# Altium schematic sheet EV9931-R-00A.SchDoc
size A3
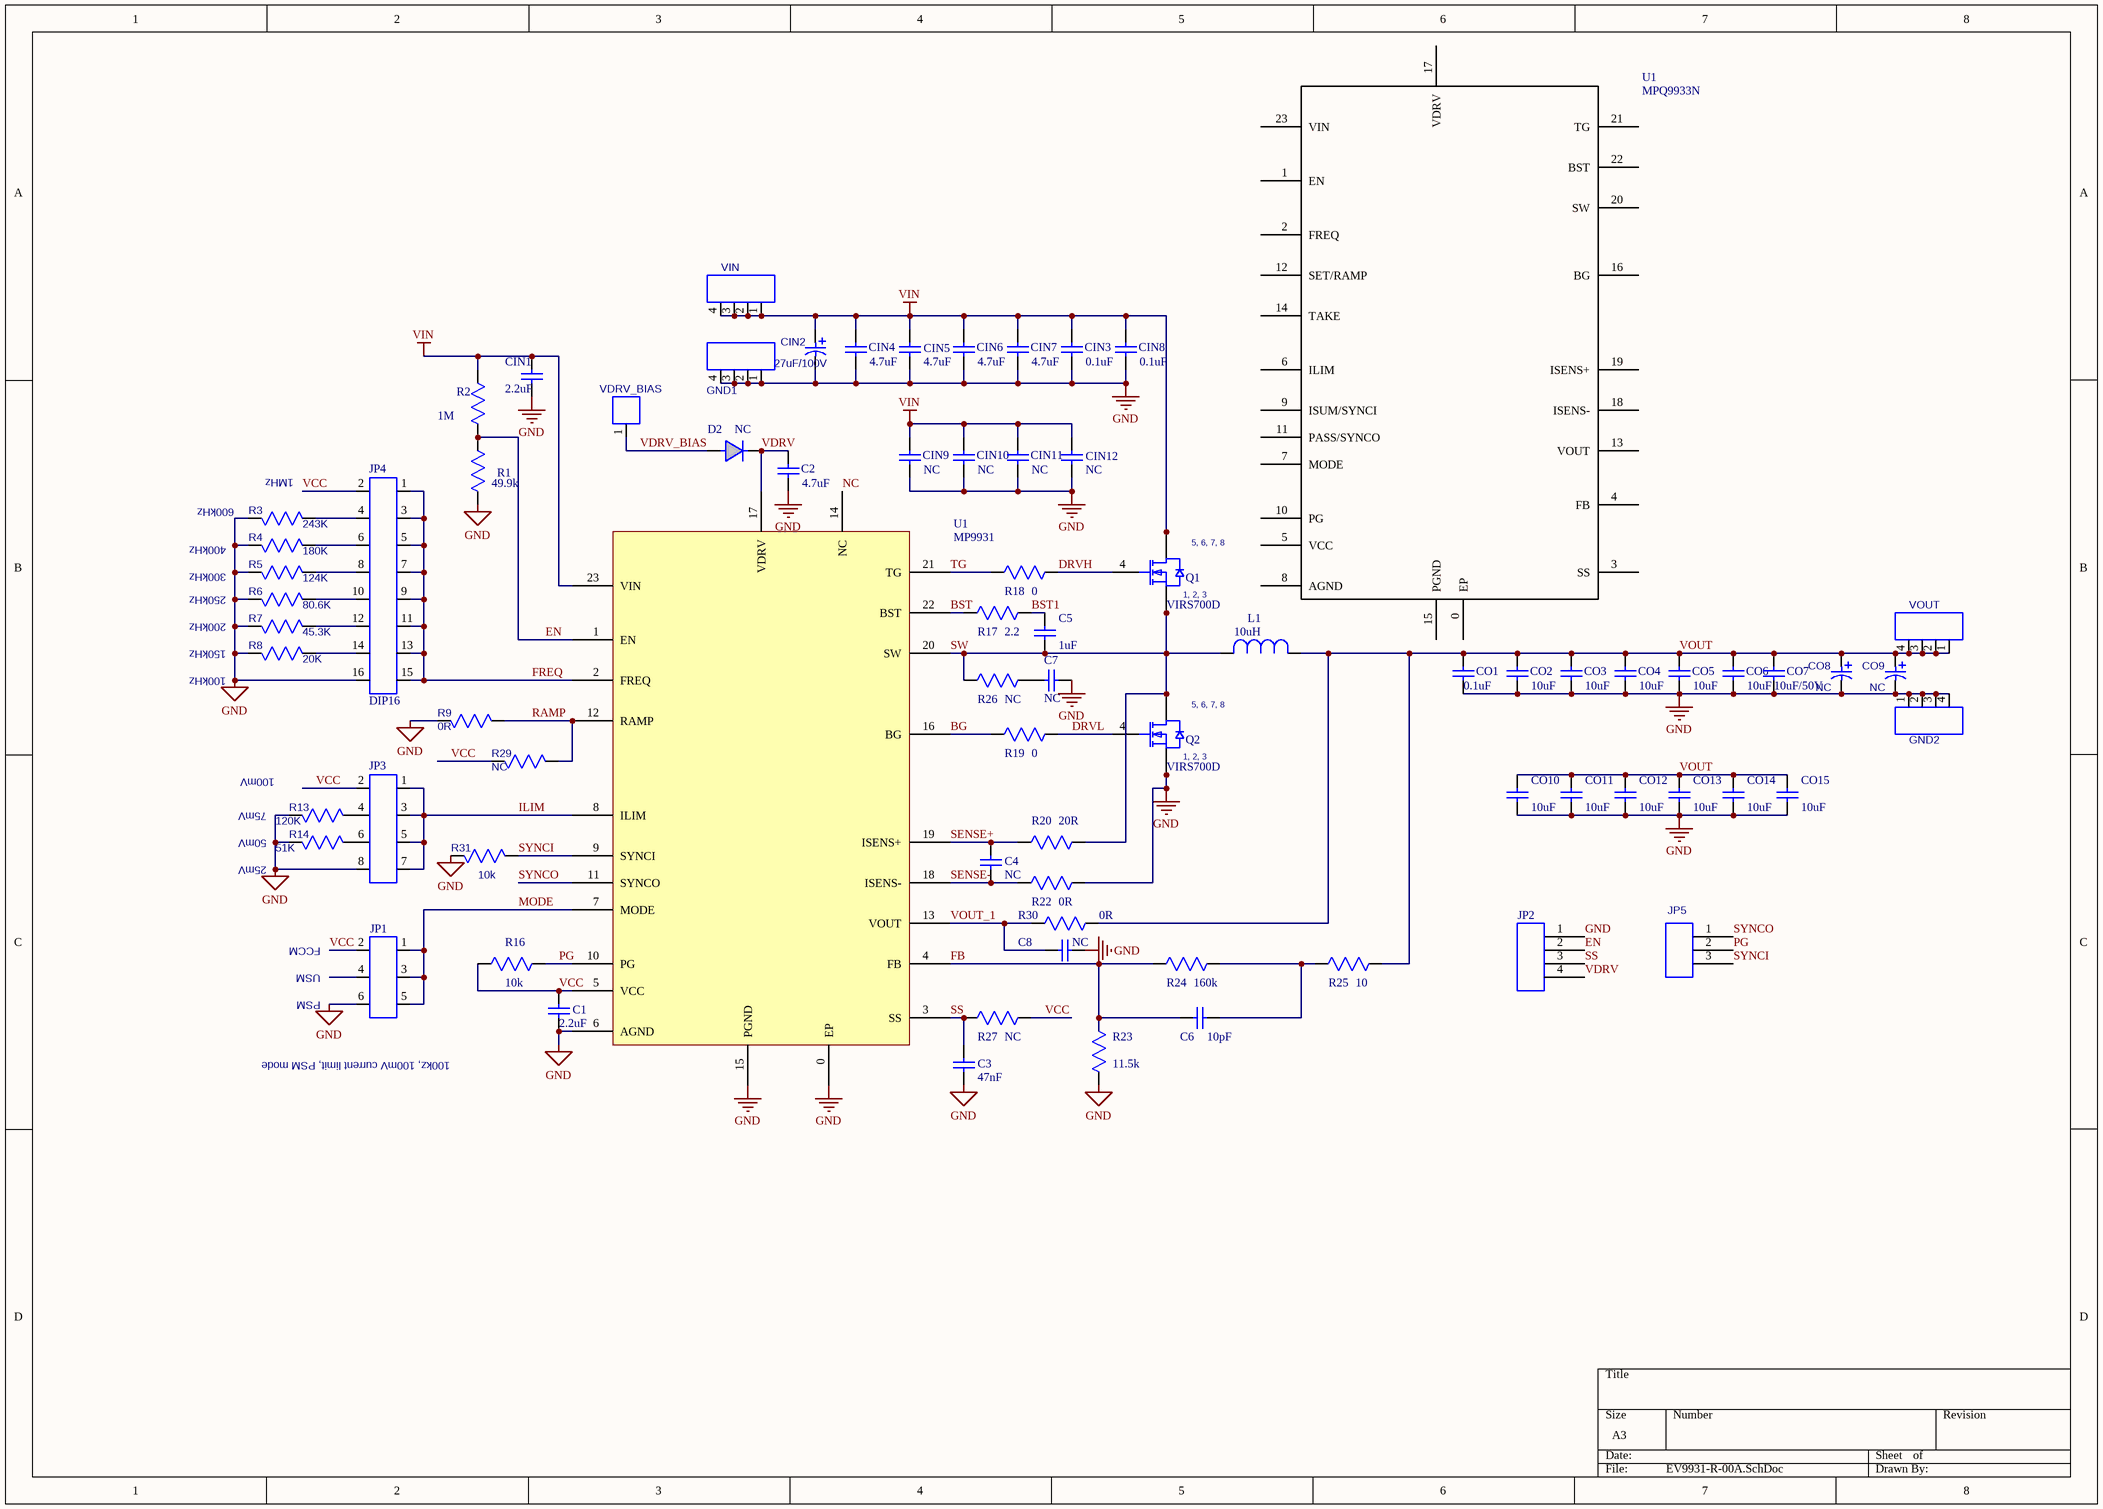
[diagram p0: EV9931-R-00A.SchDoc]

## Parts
(Parts that share a designator on the sheet are numbered #1, #2 ... from top to bottom, then left to right.)
C1  value 2.2uF  [CAP/0603]  (hidden comment: 0603)
C2  value 4.7uF  [CAP/0603]  (hidden comment: 0603)
C3  value 47nF  [CAP/0603]  (hidden comment: 0402)
C4  value NC  [CAP/0603]  (hidden comment: 0402)
C5  value 1uF  [CAP/0603]  (hidden comment: 0603)
C6  value 10pF  [CAP/0603]  (hidden comment: 0402)
C7  value NC  [CAP0805]  (hidden comment: 0402)
C8  value NC  [CAP/0603]  (hidden comment: 0603)
CIN1  value 2.2uF  [CAP/0805]  (hidden comment: 0603)
CIN2  27uF/100V  [SMD_CAP10.3*10.3MM]
CIN3  value 0.1uF  [CAP/0603]  (hidden comment: 1210)
CIN4  value 4.7uF  [CAP/1210]  (hidden comment: 1210)
CIN5  value 4.7uF  [CAP/1210]  (hidden comment: 1210)
CIN6  value 4.7uF  [CAP/1210]  (hidden comment: 1210)
CIN7  value 4.7uF  [CAP/1210]  (hidden comment: 1210)
CIN8  value 0.1uF  [CAP/0603]  (hidden comment: 1210)
CIN9  value NC  [CAP/1210]  (hidden comment: 1210)
CIN10  value NC  [CAP/1210]  (hidden comment: 1210)
CIN11  value NC  [CAP/1210]  (hidden comment: 1210)
CIN12  value NC  [CAP/1210]  (hidden comment: 1210)
CO1  value 0.1uF  [CAP/0603]  (hidden comment: 1210)
CO2  value 10uF  [CAP/1210]  (hidden comment: 1210)
CO3  value 10uF  [CAP/1210]  (hidden comment: 1210)
CO4  value 10uF  [CAP/1210]  (hidden comment: 1210)
CO5  value 10uF  [CAP/1210]  (hidden comment: 1210)
CO6  value 10uF  [CAP/1210]  (hidden comment: 1210)
CO7  value 10uF/50V  [CAP/1210]  (hidden comment: 1210)
CO8  NC  [SMD_CAP10.3*10.3MM]
CO9  NC  [SMD_CAP10.3*10.3MM]
CO10  value 10uF  [CAP/1210]  (hidden comment: 1210)
CO11  value 10uF  [CAP/1210]  (hidden comment: 1210)
CO12  value 10uF  [CAP/1210]  (hidden comment: 1210)
CO13  value 10uF  [CAP/1210]  (hidden comment: 1210)
CO14  value 10uF  [CAP/1210]  (hidden comment: 1210)
CO15  value 10uF  [CAP/1210]  (hidden comment: 1210)
D2  value NC  [SOD-123]  (hidden comment: SOD-323)
GND1  KEYSTONE7697-75  [KEYSTONE-7697-75]  (value not drawn)
GND2  KEYSTONE7697-75  [KEYSTONE-7697-75]  (value not drawn)
JP1  HEADER6  [HEADER 2X3]  (value not drawn)
JP2  HEADER 4  [CONN/DIP/4PIN/2.54MM/A]  (value not drawn)
JP3  HEADER8P  [HEADER 2X4]  (value not drawn)
JP4  DIP16  [HEADER2X8]
JP5  CONN/DIP/3PIN  [CONN/3PIN/2.54MM]  (value not drawn)
L1  value 10uH  [L23*22MM]  (hidden comment: MPL-AY1265-4R7)
Q1  value VIRS700D  (hidden comment: DFNW8)
Q2  value VIRS700D  [POWERPAK/SO-8]  (hidden comment: DFNW8)
R1  value 49.9k  [RES/0603]  (hidden comment: 0603)
R2  value 1M  [RES/0603]  (hidden comment: 0603)
R3  value 243K  [RES/0603]  (hidden comment: RES0603)
R4  value 180K  [RES/0603]  (hidden comment: RES0603)
R5  value 124K  [RES/0603]  (hidden comment: RES0603)
R6  value 80.6K  [RES/0603]  (hidden comment: RES0603)
R7  value 45.3K  [RES/0603]  (hidden comment: RES0603)
R8  value 20K  [RES/0603]  (hidden comment: RES0603)
R9  value 0R  [RES/0603]  (hidden comment: RES0603)
R13  value 120K  [RES/0603]  (hidden comment: RES0603)
R14  value 51K  [RES/0603]  (hidden comment: RES0603)
R16  value 10k  [RES/0603]  (hidden comment: 0603)
R17  value 2.2  [RES/0603]  (hidden comment: 0603)
R18  value 0  [RES/0603]  (hidden comment: 0603)
R19  value 0  [RES/0603]  (hidden comment: 0603)
R20  value 20R  [RES/0603]  (hidden comment: 0603)
R22  value 0R  [RES/0603]  (hidden comment: 0603)
R23  value 11.5k  [RES/0603]  (hidden comment: 0402)
R24  value 160k  [RES/0603]  (hidden comment: 0402)
R25  value 10  [RES/0603]  (hidden comment: 0603)
R26  value NC  [RES/1206]  (hidden comment: 0402)
R27  value NC  [RES/0603]  (hidden comment: 0603)
R29  value NC  [RES/0603]  (hidden comment: RES0603)
R30  value 0R  [RES/0603]  (hidden comment: 0402)
R31  value 10k  [RES/0603]  (hidden comment: RES0603)
U1#1  MPQ9933N  [QFN23(MP9931)]
U1#2  MP9931  [QFN23(MP9931)]
VDRV_BIAS  CONN/1MM  [header 1]  (value not drawn)
VIN  KEYSTONE7697-75  [KEYSTONE-7697-75]  (value not drawn)
VOUT  KEYSTONE7697-75  [KEYSTONE-7697-75]  (value not drawn)

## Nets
GND: C1.1 C2.2 C3.1 C7.2 C8.2 CIN1.2 CIN2.2 CIN3.2 CIN4.2 CIN5.2 CIN6.2 CIN7.2 CIN8.2 CIN9.2 CIN10.2 CIN11.2 CIN12.2 CO1.2 CO2.2 CO3.2 CO4.2 CO5.2 CO6.2 CO7.2 CO8.2 CO9.2 CO10.2 CO11.2 CO12.2 CO13.2 CO14.2 CO15.2 GND1.1 GND1.2 GND1.3 GND1.4 GND2.1 GND2.2 GND2.3 GND2.4 JP1.6 JP2.1 JP3.8 JP4.16 Q2.1(S) Q2.2(S) Q2.3(S) R1.1 R3.1 R4.1 R5.1 R6.1 R7.1 R8.1 R9.1 R13.1 R14.1 R22.2 R23.1 R31.1 U1#2.0(EP) U1#2.6(AGND) U1#2.15(PGND)
VIN: CIN1.1 CIN2.1 CIN3.1 CIN4.1 CIN5.1 CIN6.1 CIN7.1 CIN8.1 CIN9.1 CIN10.1 CIN11.1 CIN12.1 Q1.5(D) Q1.6(D) Q1.7(D) Q1.8(D) R2.2 U1#2.23(VIN) VIN.1 VIN.2 VIN.3 VIN.4
BG: R19.1 U1#2.16(BG)
BST: R17.1 U1#2.22(BST)
BST1: C5.1 R17.2
DRVH: Q1.4(G) R18.2
DRVL: Q2.4(G) R19.2
EN: JP2.2 R1.2 R2.1 U1#2.1(EN)
FB: C6.2 R23.2 R24.2 U1#2.4(FB)
FREQ: JP4.1 JP4.3 JP4.5 JP4.7 JP4.9 JP4.11 JP4.13 JP4.15 U1#2.2(FREQ)
ILIM: JP3.1 JP3.3 JP3.5 JP3.7 U1#2.8(ILIM)
MODE: JP1.1 JP1.3 JP1.5 U1#2.7(MODE)
NC: U1#2.14(NC)
PG: JP5.2 R16.2 U1#2.10(PG)
RAMP: R9.2 R29.2 U1#2.12(RAMP)
SENSE+: C4.1 R20.1 U1#2.19(ISENS+)
SENSE-: C4.2 R22.1 U1#2.18(ISENS-)
SS: C3.2 JP2.3 R27.1 U1#2.3(SS)
SW: C5.2 L1.1 Q1.1(S) Q1.2(S) Q1.3(S) Q2.5(D) Q2.6(D) Q2.7(D) Q2.8(D) R20.2 R26.2 U1#2.20(SW)
SYNCI: JP5.3 R31.2 U1#2.9(SYNCI)
SYNCO: JP5.1 U1#2.11(SYNCO)
TG: R18.1 U1#2.21(TG)
VCC: C1.2 JP1.2 JP3.2 JP4.2 R16.1 R27.2 R29.1 U1#2.5(VCC)
VDRV: C2.1 D2.2 JP2.4 U1#2.17(VDRV)
VDRV_BIAS: D2.1 VDRV_BIAS.1
VOUT: CO1.1 CO2.1 CO3.1 CO4.1 CO5.1 CO6.1 CO7.1 CO8.1 CO9.1 CO10.1 CO11.1 CO12.1 CO13.1 CO14.1 CO15.1 L1.2 R25.1 R30.1 VOUT.1 VOUT.2 VOUT.3 VOUT.4
VOUT_1: C8.1 R30.2 U1#2.13(VOUT)
NetC6_1: C6.1 R24.1 R25.2
NetC7_1: C7.1 R26.1
NetJP3_4: JP3.4 R13.2
NetJP3_6: JP3.6 R14.2
NetJP4_4: JP4.4 R3.2
NetJP4_6: JP4.6 R4.2
NetJP4_8: JP4.8 R5.2
NetJP4_10: JP4.10 R6.2
NetJP4_12: JP4.12 R7.2
NetJP4_14: JP4.14 R8.2

Not connected (* = marked no-connect by the designer): JP1 4; U1#1 0(EP) 1(EN) 2(FREQ) 3(SS) 4(FB) 5(VCC) 6(ILIM) 7(MODE) 8(AGND) 9(ISUM/SYNCI) 10(PG) 11(PASS/SYNCO) 12(SET/RAMP) 13(VOUT) 14(TAKE) 15(PGND) 16(BG) 17(VDRV) 18(ISENS-) 19(ISENS+) 20(SW) 21(TG) 22(BST) 23(VIN)

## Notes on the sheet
- 600kHz
- (near R3) 1MHz
- 300kHz
- 250kHz
- 400kHz
- 150kHz
- 200kHz
- 100kHz
- 100mV
- 25mV
- 50mV
- 75mV
- (near JP1) PSM
- (near JP1) USM
- (near JP1) FCCM
- 100kz, 100mV current limit, PSM mode

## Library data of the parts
C1-C8 CIN1 CIN3-CIN12 CO1-CO7 CO10-CO15 = Cap Semi: Capacitor (Semiconductor SIM Model)
CIN2 CO8 CO9 = CAP/OD8.0P5.0: {Description}; Manufacturer P/N: EMZJ350ADA101MF80G
D2 = 05.0084: Diode;75V;0.15A;; Part_Name: 1N4148WS; Manufacture: Diodes; Manufacture_PN: 1N4148WS-7-F; Pid: 650; Out_Num: 0; Available_Num: 4839; Note: 1N4148WS-7-F/75V/0.15A
GND1 GND2 VIN VOUT = KEYSTONE7697-75: {Description}; Manufacturer P/N: {Manufacturer P/N}; Manufacturer: {Manufacturer}
JP4 = HEADER16P
JP5 = CONN/DIP/3PIN: CONN/3PIN/2.54MM
L1 = TOKO106C
Q1 Q2 = AM4392N
R1 R2 R16 R17 R20 R22-R27 R30 = 06.0150: Film Resistor;1%; Manufacturer: Yageo; Manufacturer P/N: 9C06031A1203FKHFT; Part_Name: RC0603FR-0724K9L; Pid: 2830; Out_Num: 0; Available_Num: 2951; Note: 24.9k/1%
R3-R9 R13 R14 R29 R31 = RES0603: Manufacturer P/N: {Manufacturer P/N}; Manufacturer: {Manufacturer}; Description: {Description}
R18 R19 = 06.0150: Film Resistor;1%; Manufacturer: Yageo; Manufacturer P/N: 9C06031A1203FKHFT; Part_Name: RC0603FR-0724K9L; Pid: 2830; Available_Num: 2951; Note: 24.9k/1%
VDRV_BIAS = CONN/1MM: {Description}; Manufacturer P/N: {Manufacturer P/N}; Manufacturer: {Manufacturer}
